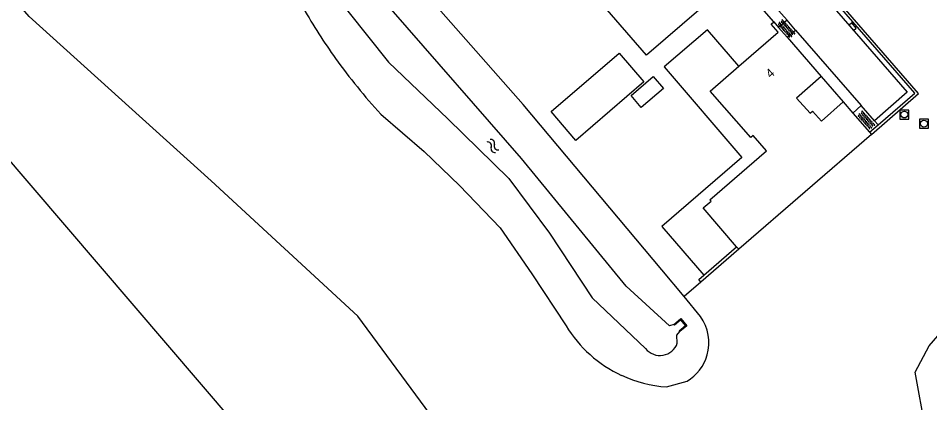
# Model space of a CAD drawing. Extents: x 128999 to 131010, y 395498 to 399007.
# Drawn here: x 129244.5 to 129345.3, y 397421.9 to 397464.4 of the extents above; entities that cross this region are included whole.
import ezdxf

# ---------------------------------------------------------------- set-up
doc = ezdxf.new("R2010")
doc.units = 0
for name, color, linetype in [('gg-afsc-muur', 7, 'Continuous'), ('gg-anno-huisnummerreeks BGT', 7, 'Continuous'), ('gg-bbg-gedigitaliseerde bijgebouw', 7, 'Continuous'), ('gg-bbg-hoofdgebouw', 7, 'Continuous'), ('gg-bbg-luifel en loopbrug', 7, 'Continuous'), ('gg-knt-verharding', 7, 'Continuous'), ('gg-knt-verharding nz', 7, 'Continuous'), ('gg-kntw-bovenkant insteek waterloop', 7, 'Continuous'), ('gg-kntw-midden sloot', 7, 'Continuous'), ('gg-kntw-waterlijn', 7, 'Continuous'), ('gg-kwrk-uitstroombak niveau min 01', 7, 'Continuous'), ('gt-grn-groengrens', 7, 'Continuous'), ('gt-grn-vlakafsluiter', 7, 'Continuous'), ('gt-symb-kolk', 7, 'Continuous'), ('gt-symb-overige verharding', 7, 'Continuous'), ('gt-symb-rioolschacht', 7, 'Continuous'), ('gt-symb-watersymbool', 7, 'Continuous')]:
    doc.layers.add(name, color=color, linetype=linetype)

# ---------------------------------------------------------------- blocks, each defined once
blk = doc.blocks.new('gt0-OVH')
at = {"layer": 'gt-symb-overige verharding'}
for points in [[(-0.97, 0.3), (-0.97, 0.31), (-0.96, 0.32), (-0.97, 0.33), (-0.97, 0.34), (-0.98, 0.35), (-0.99, 0.35), (-1, 0.36), (-1.01, 0.35), (-1.02, 0.35), (-1.03, 0.34), (-1.03, 0.33), (-1.04, 0.32), (-1.03, 0.31), (-1.03, 0.3), (-1.02, 0.29), (-1.01, 0.29), (-1, 0.28), (-0.99, 0.29), (-0.98, 0.29)], [(-0.87, 0.11), (-0.87, 0.12), (-0.86, 0.13), (-0.87, 0.14), (-0.87, 0.15), (-0.88, 0.16), (-0.89, 0.16), (-0.9, 0.16), (-0.91, 0.16), (-0.92, 0.16), (-0.93, 0.15), (-0.93, 0.14), (-0.94, 0.13), (-0.93, 0.12), (-0.93, 0.11), (-0.92, 0.1), (-0.91, 0.09), (-0.9, 0.09), (-0.89, 0.09), (-0.88, 0.1)], [(-0.77, 0.3), (-0.77, 0.31), (-0.76, 0.32), (-0.77, 0.33), (-0.77, 0.34), (-0.78, 0.35), (-0.79, 0.35), (-0.8, 0.36), (-0.81, 0.35), (-0.82, 0.35), (-0.83, 0.34), (-0.83, 0.33), (-0.84, 0.32), (-0.83, 0.31), (-0.83, 0.3), (-0.82, 0.29), (-0.81, 0.29), (-0.8, 0.28), (-0.79, 0.29), (-0.78, 0.29)], [(-0.67, 0.11), (-0.67, 0.12), (-0.66, 0.13), (-0.67, 0.14), (-0.67, 0.15), (-0.68, 0.16), (-0.69, 0.16), (-0.7, 0.16), (-0.71, 0.16), (-0.72, 0.16), (-0.73, 0.15), (-0.73, 0.14), (-0.74, 0.13), (-0.73, 0.12), (-0.73, 0.11), (-0.72, 0.1), (-0.71, 0.09), (-0.7, 0.09), (-0.69, 0.09), (-0.68, 0.1)], [(-0.57, 0.3), (-0.57, 0.31), (-0.56, 0.32), (-0.57, 0.33), (-0.57, 0.34), (-0.58, 0.35), (-0.59, 0.35), (-0.6, 0.36), (-0.61, 0.35), (-0.62, 0.35), (-0.63, 0.34), (-0.63, 0.33), (-0.64, 0.32), (-0.63, 0.31), (-0.63, 0.3), (-0.62, 0.29), (-0.61, 0.29), (-0.6, 0.28), (-0.59, 0.29), (-0.58, 0.29)], [(-0.47, 0.11), (-0.47, 0.12), (-0.46, 0.13), (-0.47, 0.14), (-0.47, 0.15), (-0.48, 0.16), (-0.49, 0.16), (-0.5, 0.16), (-0.51, 0.16), (-0.52, 0.16), (-0.53, 0.15), (-0.53, 0.14), (-0.54, 0.13), (-0.53, 0.12), (-0.53, 0.11), (-0.52, 0.1), (-0.51, 0.09), (-0.5, 0.09), (-0.49, 0.09), (-0.48, 0.1)], [(-0.37, 0.3), (-0.37, 0.31), (-0.36, 0.32), (-0.37, 0.33), (-0.37, 0.34), (-0.38, 0.35), (-0.39, 0.35), (-0.4, 0.36), (-0.41, 0.35), (-0.42, 0.35), (-0.43, 0.34), (-0.43, 0.33), (-0.44, 0.32), (-0.43, 0.31), (-0.43, 0.3), (-0.42, 0.29), (-0.41, 0.29), (-0.4, 0.28), (-0.39, 0.29), (-0.38, 0.29)], [(-0.27, 0.11), (-0.27, 0.12), (-0.26, 0.13), (-0.27, 0.14), (-0.27, 0.15), (-0.28, 0.16), (-0.29, 0.16), (-0.3, 0.16), (-0.31, 0.16), (-0.32, 0.16), (-0.33, 0.15), (-0.33, 0.14), (-0.34, 0.13), (-0.33, 0.12), (-0.33, 0.11), (-0.32, 0.1), (-0.31, 0.09), (-0.3, 0.09), (-0.29, 0.09), (-0.28, 0.1)], [(-0.17, 0.3), (-0.17, 0.31), (-0.16, 0.32), (-0.17, 0.33), (-0.17, 0.34), (-0.18, 0.35), (-0.19, 0.35), (-0.2, 0.36), (-0.21, 0.35), (-0.22, 0.35), (-0.23, 0.34), (-0.23, 0.33), (-0.24, 0.32), (-0.23, 0.31), (-0.23, 0.3), (-0.22, 0.29), (-0.21, 0.29), (-0.2, 0.28), (-0.19, 0.29), (-0.18, 0.29)], [(-0.07, 0.11), (-0.07, 0.12), (-0.06, 0.13), (-0.07, 0.14), (-0.07, 0.15), (-0.08, 0.16), (-0.09, 0.16), (-0.1, 0.16), (-0.11, 0.16), (-0.12, 0.16), (-0.13, 0.15), (-0.13, 0.14), (-0.14, 0.13), (-0.13, 0.12), (-0.13, 0.11), (-0.12, 0.1), (-0.11, 0.09), (-0.1, 0.09), (-0.09, 0.09), (-0.08, 0.1)], [(0.03, 0.3), (0.03, 0.31), (0.04, 0.32), (0.03, 0.33), (0.03, 0.34), (0.02, 0.35), (0.01, 0.35), (0, 0.36), (-0.01, 0.35), (-0.02, 0.35), (-0.03, 0.34), (-0.03, 0.33), (-0.04, 0.32), (-0.03, 0.31), (-0.03, 0.3), (-0.02, 0.29), (-0.01, 0.29), (0, 0.28), (0.01, 0.29), (0.02, 0.29)], [(0.13, 0.11), (0.13, 0.12), (0.14, 0.13), (0.13, 0.14), (0.13, 0.15), (0.12, 0.16), (0.11, 0.16), (0.1, 0.16), (0.09, 0.16), (0.08, 0.16), (0.07, 0.15), (0.07, 0.14), (0.06, 0.13), (0.07, 0.12), (0.07, 0.11), (0.08, 0.1), (0.09, 0.09), (0.1, 0.09), (0.11, 0.09), (0.12, 0.1)], [(0.23, 0.3), (0.23, 0.31), (0.24, 0.32), (0.23, 0.33), (0.23, 0.34), (0.22, 0.35), (0.21, 0.35), (0.2, 0.36), (0.19, 0.35), (0.18, 0.35), (0.17, 0.34), (0.17, 0.33), (0.16, 0.32), (0.17, 0.31), (0.17, 0.3), (0.18, 0.29), (0.19, 0.29), (0.2, 0.28), (0.21, 0.29), (0.22, 0.29)], [(0.33, 0.11), (0.33, 0.12), (0.34, 0.13), (0.33, 0.14), (0.33, 0.15), (0.32, 0.16), (0.31, 0.16), (0.3, 0.16), (0.29, 0.16), (0.28, 0.16), (0.27, 0.15), (0.27, 0.14), (0.26, 0.13), (0.27, 0.12), (0.27, 0.11), (0.28, 0.1), (0.29, 0.09), (0.3, 0.09), (0.31, 0.09), (0.32, 0.1)], [(0.43, 0.3), (0.43, 0.31), (0.44, 0.32), (0.43, 0.33), (0.43, 0.34), (0.42, 0.35), (0.41, 0.35), (0.4, 0.36), (0.39, 0.35), (0.38, 0.35), (0.37, 0.34), (0.37, 0.33), (0.36, 0.32), (0.37, 0.31), (0.37, 0.3), (0.38, 0.29), (0.39, 0.29), (0.4, 0.28), (0.41, 0.29), (0.42, 0.29)], [(0.53, 0.11), (0.53, 0.12), (0.54, 0.13), (0.53, 0.14), (0.53, 0.15), (0.52, 0.16), (0.51, 0.16), (0.5, 0.16), (0.49, 0.16), (0.48, 0.16), (0.47, 0.15), (0.47, 0.14), (0.46, 0.13), (0.47, 0.12), (0.47, 0.11), (0.48, 0.1), (0.49, 0.09), (0.5, 0.09), (0.51, 0.09), (0.52, 0.1)], [(0.63, 0.3), (0.63, 0.31), (0.64, 0.32), (0.63, 0.33), (0.63, 0.34), (0.62, 0.35), (0.61, 0.35), (0.6, 0.36), (0.59, 0.35), (0.58, 0.35), (0.57, 0.34), (0.57, 0.33), (0.56, 0.32), (0.57, 0.31), (0.57, 0.3), (0.58, 0.29), (0.59, 0.29), (0.6, 0.28), (0.61, 0.29), (0.62, 0.29)], [(0.73, 0.11), (0.73, 0.12), (0.74, 0.13), (0.73, 0.14), (0.73, 0.15), (0.72, 0.16), (0.71, 0.16), (0.7, 0.16), (0.69, 0.16), (0.68, 0.16), (0.67, 0.15), (0.67, 0.14), (0.66, 0.13), (0.67, 0.12), (0.67, 0.11), (0.68, 0.1), (0.69, 0.09), (0.7, 0.09), (0.71, 0.09), (0.72, 0.1)], [(0.83, 0.3), (0.83, 0.31), (0.84, 0.32), (0.83, 0.33), (0.83, 0.34), (0.82, 0.35), (0.81, 0.35), (0.8, 0.36), (0.79, 0.35), (0.78, 0.35), (0.77, 0.34), (0.77, 0.33), (0.76, 0.32), (0.77, 0.31), (0.77, 0.3), (0.78, 0.29), (0.79, 0.29), (0.8, 0.28), (0.81, 0.29), (0.82, 0.29)], [(0.93, 0.11), (0.93, 0.12), (0.94, 0.13), (0.93, 0.14), (0.93, 0.15), (0.92, 0.16), (0.91, 0.16), (0.9, 0.16), (0.89, 0.16), (0.88, 0.16), (0.87, 0.15), (0.87, 0.14), (0.86, 0.13), (0.87, 0.12), (0.87, 0.11), (0.88, 0.1), (0.89, 0.09), (0.9, 0.09), (0.91, 0.09), (0.92, 0.1)], [(1.03, 0.3), (1.03, 0.31), (1.04, 0.32), (1.03, 0.33), (1.03, 0.34), (1.02, 0.35), (1.01, 0.35), (1, 0.36), (0.99, 0.35), (0.98, 0.35), (0.97, 0.34), (0.97, 0.33), (0.96, 0.32), (0.97, 0.31), (0.97, 0.3), (0.98, 0.29), (0.99, 0.29), (1, 0.28), (1.01, 0.29), (1.02, 0.29)], [(-0.97, -0.14), (-0.97, -0.13), (-0.96, -0.12), (-0.97, -0.11), (-0.97, -0.1), (-0.98, -0.09), (-0.99, -0.09), (-1, -0.08), (-1.01, -0.09), (-1.02, -0.09), (-1.03, -0.1), (-1.03, -0.11), (-1.04, -0.12), (-1.03, -0.13), (-1.03, -0.14), (-1.02, -0.15), (-1.01, -0.15), (-1, -0.16), (-0.99, -0.15), (-0.98, -0.15)], [(-0.87, -0.33), (-0.87, -0.32), (-0.86, -0.31), (-0.87, -0.3), (-0.87, -0.29), (-0.88, -0.28), (-0.89, -0.28), (-0.9, -0.28), (-0.91, -0.28), (-0.92, -0.28), (-0.93, -0.29), (-0.93, -0.3), (-0.94, -0.31), (-0.93, -0.32), (-0.93, -0.33), (-0.92, -0.34), (-0.91, -0.35), (-0.9, -0.35), (-0.89, -0.35), (-0.88, -0.34)], [(-0.77, -0.14), (-0.77, -0.13), (-0.76, -0.12), (-0.77, -0.11), (-0.77, -0.1), (-0.78, -0.09), (-0.79, -0.09), (-0.8, -0.08), (-0.81, -0.09), (-0.82, -0.09), (-0.83, -0.1), (-0.83, -0.11), (-0.84, -0.12), (-0.83, -0.13), (-0.83, -0.14), (-0.82, -0.15), (-0.81, -0.15), (-0.8, -0.16), (-0.79, -0.15), (-0.78, -0.15)], [(-0.67, -0.33), (-0.67, -0.32), (-0.66, -0.31), (-0.67, -0.3), (-0.67, -0.29), (-0.68, -0.28), (-0.69, -0.28), (-0.7, -0.28), (-0.71, -0.28), (-0.72, -0.28), (-0.73, -0.29), (-0.73, -0.3), (-0.74, -0.31), (-0.73, -0.32), (-0.73, -0.33), (-0.72, -0.34), (-0.71, -0.35), (-0.7, -0.35), (-0.69, -0.35), (-0.68, -0.34)], [(-0.57, -0.14), (-0.57, -0.13), (-0.56, -0.12), (-0.57, -0.11), (-0.57, -0.1), (-0.58, -0.09), (-0.59, -0.09), (-0.6, -0.08), (-0.61, -0.09), (-0.62, -0.09), (-0.63, -0.1), (-0.63, -0.11), (-0.64, -0.12), (-0.63, -0.13), (-0.63, -0.14), (-0.62, -0.15), (-0.61, -0.15), (-0.6, -0.16), (-0.59, -0.15), (-0.58, -0.15)], [(-0.47, -0.33), (-0.47, -0.32), (-0.46, -0.31), (-0.47, -0.3), (-0.47, -0.29), (-0.48, -0.28), (-0.49, -0.28), (-0.5, -0.28), (-0.51, -0.28), (-0.52, -0.28), (-0.53, -0.29), (-0.53, -0.3), (-0.54, -0.31), (-0.53, -0.32), (-0.53, -0.33), (-0.52, -0.34), (-0.51, -0.35), (-0.5, -0.35), (-0.49, -0.35), (-0.48, -0.34)], [(-0.37, -0.14), (-0.37, -0.13), (-0.36, -0.12), (-0.37, -0.11), (-0.37, -0.1), (-0.38, -0.09), (-0.39, -0.09), (-0.4, -0.08), (-0.41, -0.09), (-0.42, -0.09), (-0.43, -0.1), (-0.43, -0.11), (-0.44, -0.12), (-0.43, -0.13), (-0.43, -0.14), (-0.42, -0.15), (-0.41, -0.15), (-0.4, -0.16), (-0.39, -0.15), (-0.38, -0.15)], [(-0.27, -0.33), (-0.27, -0.32), (-0.26, -0.31), (-0.27, -0.3), (-0.27, -0.29), (-0.28, -0.28), (-0.29, -0.28), (-0.3, -0.28), (-0.31, -0.28), (-0.32, -0.28), (-0.33, -0.29), (-0.33, -0.3), (-0.34, -0.31), (-0.33, -0.32), (-0.33, -0.33), (-0.32, -0.34), (-0.31, -0.35), (-0.3, -0.35), (-0.29, -0.35), (-0.28, -0.34)], [(-0.17, -0.14), (-0.17, -0.13), (-0.16, -0.12), (-0.17, -0.11), (-0.17, -0.1), (-0.18, -0.09), (-0.19, -0.09), (-0.2, -0.08), (-0.21, -0.09), (-0.22, -0.09), (-0.23, -0.1), (-0.23, -0.11), (-0.24, -0.12), (-0.23, -0.13), (-0.23, -0.14), (-0.22, -0.15), (-0.21, -0.15), (-0.2, -0.16), (-0.19, -0.15), (-0.18, -0.15)], [(-0.07, -0.33), (-0.07, -0.32), (-0.06, -0.31), (-0.07, -0.3), (-0.07, -0.29), (-0.08, -0.28), (-0.09, -0.28), (-0.1, -0.28), (-0.11, -0.28), (-0.12, -0.28), (-0.13, -0.29), (-0.13, -0.3), (-0.14, -0.31), (-0.13, -0.32), (-0.13, -0.33), (-0.12, -0.34), (-0.11, -0.35), (-0.1, -0.35), (-0.09, -0.35), (-0.08, -0.34)], [(0.03, -0.14), (0.03, -0.13), (0.04, -0.12), (0.03, -0.11), (0.03, -0.1), (0.02, -0.09), (0.01, -0.09), (0, -0.08), (-0.01, -0.09), (-0.02, -0.09), (-0.03, -0.1), (-0.03, -0.11), (-0.04, -0.12), (-0.03, -0.13), (-0.03, -0.14), (-0.02, -0.15), (-0.01, -0.15), (0, -0.16), (0.01, -0.15), (0.02, -0.15)], [(0.13, -0.33), (0.13, -0.32), (0.14, -0.31), (0.13, -0.3), (0.13, -0.29), (0.12, -0.28), (0.11, -0.28), (0.1, -0.28), (0.09, -0.28), (0.08, -0.28), (0.07, -0.29), (0.07, -0.3), (0.06, -0.31), (0.07, -0.32), (0.07, -0.33), (0.08, -0.34), (0.09, -0.35), (0.1, -0.35), (0.11, -0.35), (0.12, -0.34)], [(0.23, -0.14), (0.23, -0.13), (0.24, -0.12), (0.23, -0.11), (0.23, -0.1), (0.22, -0.09), (0.21, -0.09), (0.2, -0.08), (0.19, -0.09), (0.18, -0.09), (0.17, -0.1), (0.17, -0.11), (0.16, -0.12), (0.17, -0.13), (0.17, -0.14), (0.18, -0.15), (0.19, -0.15), (0.2, -0.16), (0.21, -0.15), (0.22, -0.15)], [(0.33, -0.33), (0.33, -0.32), (0.34, -0.31), (0.33, -0.3), (0.33, -0.29), (0.32, -0.28), (0.31, -0.28), (0.3, -0.28), (0.29, -0.28), (0.28, -0.28), (0.27, -0.29), (0.27, -0.3), (0.26, -0.31), (0.27, -0.32), (0.27, -0.33), (0.28, -0.34), (0.29, -0.35), (0.3, -0.35), (0.31, -0.35), (0.32, -0.34)], [(0.43, -0.14), (0.43, -0.13), (0.44, -0.12), (0.43, -0.11), (0.43, -0.1), (0.42, -0.09), (0.41, -0.09), (0.4, -0.08), (0.39, -0.09), (0.38, -0.09), (0.37, -0.1), (0.37, -0.11), (0.36, -0.12), (0.37, -0.13), (0.37, -0.14), (0.38, -0.15), (0.39, -0.15), (0.4, -0.16), (0.41, -0.15), (0.42, -0.15)], [(0.53, -0.33), (0.53, -0.32), (0.54, -0.31), (0.53, -0.3), (0.53, -0.29), (0.52, -0.28), (0.51, -0.28), (0.5, -0.28), (0.49, -0.28), (0.48, -0.28), (0.47, -0.29), (0.47, -0.3), (0.46, -0.31), (0.47, -0.32), (0.47, -0.33), (0.48, -0.34), (0.49, -0.35), (0.5, -0.35), (0.51, -0.35), (0.52, -0.34)], [(0.63, -0.14), (0.63, -0.13), (0.64, -0.12), (0.63, -0.11), (0.63, -0.1), (0.62, -0.09), (0.61, -0.09), (0.6, -0.08), (0.59, -0.09), (0.58, -0.09), (0.57, -0.1), (0.57, -0.11), (0.56, -0.12), (0.57, -0.13), (0.57, -0.14), (0.58, -0.15), (0.59, -0.15), (0.6, -0.16), (0.61, -0.15), (0.62, -0.15)], [(0.73, -0.33), (0.73, -0.32), (0.74, -0.31), (0.73, -0.3), (0.73, -0.29), (0.72, -0.28), (0.71, -0.28), (0.7, -0.28), (0.69, -0.28), (0.68, -0.28), (0.67, -0.29), (0.67, -0.3), (0.66, -0.31), (0.67, -0.32), (0.67, -0.33), (0.68, -0.34), (0.69, -0.35), (0.7, -0.35), (0.71, -0.35), (0.72, -0.34)], [(0.83, -0.14), (0.83, -0.13), (0.84, -0.12), (0.83, -0.11), (0.83, -0.1), (0.82, -0.09), (0.81, -0.09), (0.8, -0.08), (0.79, -0.09), (0.78, -0.09), (0.77, -0.1), (0.77, -0.11), (0.76, -0.12), (0.77, -0.13), (0.77, -0.14), (0.78, -0.15), (0.79, -0.15), (0.8, -0.16), (0.81, -0.15), (0.82, -0.15)], [(0.93, -0.33), (0.93, -0.32), (0.94, -0.31), (0.93, -0.3), (0.93, -0.29), (0.92, -0.28), (0.91, -0.28), (0.9, -0.28), (0.89, -0.28), (0.88, -0.28), (0.87, -0.29), (0.87, -0.3), (0.86, -0.31), (0.87, -0.32), (0.87, -0.33), (0.88, -0.34), (0.89, -0.35), (0.9, -0.35), (0.91, -0.35), (0.92, -0.34)], [(1.03, -0.14), (1.03, -0.13), (1.04, -0.12), (1.03, -0.11), (1.03, -0.1), (1.02, -0.09), (1.01, -0.09), (1, -0.08), (0.99, -0.09), (0.98, -0.09), (0.97, -0.1), (0.97, -0.11), (0.96, -0.12), (0.97, -0.13), (0.97, -0.14), (0.98, -0.15), (0.99, -0.15), (1, -0.16), (1.01, -0.15), (1.02, -0.15)]]:
    blk.add_lwpolyline(points, close=True, dxfattribs=at)
blk = doc.blocks.new('gt0-RS')
at = {"layer": 'gt-symb-rioolschacht'}
blk.add_lwpolyline([(-0.5, -0.5), (0.5, -0.5), (0.5, 0.5), (-0.5, 0.5)], close=True, dxfattribs=at)
blk.add_circle((0, 0), 0.375, dxfattribs=at)
blk = doc.blocks.new('gt0-WA')
at = {"layer": 'gt-symb-watersymbool'}
for centre, start, end in [((-0.32, 0.02), 28.0725, 151.9275), ((0.43, 0.42), 208.0725, 331.9275), ((-0.32, -0.43), 28.0725, 151.9275), ((0.43, -0.03), 208.0725, 331.9275)]:
    blk.add_arc(centre, 0.425, start, end, dxfattribs=at)
blk = doc.blocks.new('gt0-KOLK')
at = {"layer": 'gt-symb-kolk'}
blk.add_lwpolyline([(0, 0), (0.38, 0), (0.38, 0.4), (-0.38, 0.4), (-0.38, 0), (0, 0)], dxfattribs=at)

msp = doc.modelspace()

# ---------------------------------------------------------------- linework, layer by layer
at = {"layer": 'gg-afsc-muur'}
for p, q in [((129338.62, 397451.82), (129339.56, 397452.64)), ((129324.16, 397438.9), (129319.98, 397435.28))]:
    msp.add_line(p, q, dxfattribs=at)
for points in [[(129339.56, 397452.64), (129343.61, 397456.15), (129293.45, 397513.91)], [(129338.82, 397451.59), (129344.01, 397456.11), (129293.67, 397514.09), (129293.6, 397514.03)], [(129319.98, 397435.28), (129319.74, 397435.57), (129320.29, 397436.05)]]:
    msp.add_lwpolyline(points, dxfattribs=at)
at = {"layer": 'gg-bbg-gedigitaliseerde bijgebouw'}
for points in [[(129303.44, 397454.11), (129310.93, 397460.56), (129313.66, 397457.38), (129306.17, 397450.93), (129303.44, 397454.11)], [(129312.26, 397455.87), (129314.7, 397457.97), (129315.83, 397456.65), (129313.39, 397454.56), (129312.26, 397455.87)]]:
    msp.add_lwpolyline(points, dxfattribs=at)
at = {"layer": 'gg-bbg-hoofdgebouw'}
for p, q in [((129328.04, 397464.01), (129328.57, 397463.4)), ((129328.57, 397463.4), (129329.5, 397462.33)), ((129329.5, 397462.33), (129333.26, 397457.98)), ((129335.69, 397455.19), (129336.77, 397453.95)), ((129336.77, 397453.95), (129338.62, 397451.82)), ((129338.82, 397451.59), (129324.16, 397438.9)), ((129338.62, 397451.82), (129338.82, 397451.59)), ((129323.91, 397439.18), (129324.16, 397438.9))]:
    msp.add_line(p, q, dxfattribs=at)
for points in [[(129321.79, 397471.19), (129321.51, 397470.94), (129321.33, 397471.14), (129317.84, 397468.11), (129320, 397465.52), (129313.98, 397460.34), (129307.18, 397468.2)], [(129324.17, 397459.11), (129328.51, 397462.87), (129327.75, 397463.75), (129328.04, 397464.01)], [(129323.91, 397439.18), (129320.24, 397443.47), (129321.11, 397444.22), (129320.98, 397444.37), (129327.23, 397449.79), (129325.76, 397451.48), (129325.48, 397451.24), (129321.01, 397456.38), (129324.17, 397459.11)], [(129333.26, 397457.98), (129330.56, 397455.61), (129332.04, 397453.92), (129332.31, 397454.16), (129333.3, 397453.05), (129335.69, 397455.19)]]:
    msp.add_lwpolyline(points, dxfattribs=at)
at = {"layer": 'gg-bbg-luifel en loopbrug'}
msp.add_line((129320.29, 397436.05), (129323.91, 397439.18), dxfattribs=at)
msp.add_lwpolyline([(129324.17, 397459.11), (129320.7, 397463.15), (129315.92, 397459.04), (129324.51, 397449.05), (129315.65, 397441.43), (129320.29, 397436.05)], dxfattribs=at)
at = {"layer": 'gg-knt-verharding'}
for p, q in [((129328.04, 397464.01), (129321.79, 397471.19)), ((129329.51, 397464.21), (129328.57, 397463.4)), ((129330.44, 397463.12), (129329.51, 397464.21)), ((129329.5, 397462.33), (129330.44, 397463.12)), ((129333.26, 397457.98), (129335.69, 397455.19)), ((129337.69, 397454.77), (129336.77, 397453.95)), ((129339.16, 397453.09), (129337.69, 397454.77)), ((129339.16, 397453.09), (129339.56, 397452.64))]:
    msp.add_line(p, q, dxfattribs=at)
msp.add_lwpolyline([(129293.01, 397513.55), (129342.78, 397456.24), (129339.16, 397453.09)], dxfattribs=at)
at = {"layer": 'gg-knt-verharding nz'}
for p, q in [((129329.51, 397464.21), (129321.7, 397473.18)), ((129330.44, 397463.12), (129337.69, 397454.77))]:
    msp.add_line(p, q, dxfattribs=at)
at = {"layer": 'gg-kntw-bovenkant insteek waterloop'}
for p, q in [((129319.95, 397431.46), (129318.12, 397433.68)), ((129316.18, 397423.68), (129318.45, 397424.31))]:
    msp.add_line(p, q, dxfattribs=at)
for points in [[(129318.12, 397433.68), (129315.67, 397436.63), (129300.35, 397454.89), (129284.89, 397472.43), (129273.71, 397484.65), (129269.01, 397490.89)], [(129284.59, 397453.81), (129289.41, 397449.71), (129293.3, 397445.94), (129297.78, 397441.25), (129301.28, 397436.17), (129305.08, 397430.45)], [(129376.5, 397433.58), (129380.7, 397432.48), (129382.93, 397430.88), (129386.13, 397426.66), (129386.97, 397421.78), (129385.36, 397415.89), (129381.92, 397411.5), (129377.31, 397408.84), (129373.04, 397407.77), (129366.6, 397407.37), (129356.13, 397409.28), (129350.93, 397411.08), (129346.58, 397414.83), (129344.8, 397419.06), (129343.66, 397425.31), (129345.22, 397428.24), (129347.82, 397431.23), (129352.41, 397433.27), (129358.81, 397434.6), (129376.5, 397433.58)]]:
    msp.add_lwpolyline(points, dxfattribs=at)
for centre, radius, start, end in [((129334.34, 397499.05), 67.25, 209.904, 215.5236), ((129334.04, 397498.88), 66.9, 215.5511, 222.3442), ((129315.87, 397428.58), 4.99, 344.183, 35.2023), ((129317.2, 397437.85), 14.21, 211.3951, 245.0427), ((129315.87, 397428.58), 4.99, 301.0749, 344.1714), ((129317.2, 397437.85), 14.2, 245.0606, 265.9041)]:
    msp.add_arc(centre, radius, start, end, dxfattribs=at)
at = {"layer": 'gg-kntw-midden sloot'}
msp.add_line((129328.36, 397349.84), (129202.93, 397496.1), dxfattribs=at)
at = {"layer": 'gg-kntw-waterlijn'}
for points in [[(129317, 397430.59), (129316.5, 397430.43), (129311.71, 397434.83), (129300.15, 397448.92), (129285.74, 397465.42), (129277.5, 397474.65), (129266.69, 397485.84), (129263.56, 397488.27), (129261.44, 397491.39)], [(129255.99, 397489.84), (129259.63, 397487.49), (129261.24, 397486.53), (129262.81, 397485.52), (129264.52, 397484.37), (129266.19, 397483.17), (129269.8, 397479.19), (129274.35, 397473.86), (129280.95, 397465.21), (129285.46, 397459.56), (129292, 397453.3), (129298.76, 397446.7), (129303.23, 397440.68), (129307.95, 397433.52), (129313.86, 397427.93)], [(129317.37, 397428.53), (129317.33, 397429.42), (129317.64, 397429.82)]]:
    msp.add_lwpolyline(points, dxfattribs=at)
for start, end in [(218.3401, 279.9093), (279.9611, 341.1332)]:
    msp.add_arc((129315.45, 397429.19), 2.03, start, end, dxfattribs=at)
at = {"layer": 'gg-kwrk-uitstroombak niveau min 01'}
for points in [[(129317, 397430.59), (129317.77, 397431.23), (129318.41, 397430.45), (129317.64, 397429.82)], [(129317.64, 397429.82), (129317.58, 397429.9), (129318.27, 397430.47), (129317.76, 397431.09), (129317.06, 397430.52), (129317, 397430.59)]]:
    msp.add_lwpolyline(points, dxfattribs=at)
at = {"layer": 'gt-grn-groengrens'}
msp.add_lwpolyline([(129310.83, 397401.47), (129308.04, 397404.26), (129291.17, 397419.18), (129282.08, 397431.51), (129265.86, 397446.44), (129245.74, 397464.61), (129232.76, 397479.53), (129211.35, 397497.7), (129181.5, 397535.99), (129170.42, 397548.18)], dxfattribs=at)
at = {"layer": 'gt-grn-vlakafsluiter'}
msp.add_line((129319.98, 397435.28), (129318.12, 397433.68), dxfattribs=at)

# ---------------------------------------------------------------- block references
at = {"layer": 'gt-symb-kolk', "rotation": -49.031951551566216}
msp.add_blockref('gt0-KOLK', (129336.6, 397463.36), dxfattribs=at)
at = {"layer": 'gt-symb-overige verharding', "rotation": -47.79566231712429}
for p in [(129329.41, 397463.27), (129338.24, 397453.16)]:
    msp.add_blockref('gt0-OVH', p, dxfattribs=at)
at = {"layer": 'gt-symb-rioolschacht'}
for p in [(129342.46, 397453.78), (129344.63, 397452.78)]:
    msp.add_blockref('gt0-RS', p, dxfattribs=at)
at = {"layer": 'gt-symb-watersymbool', "rotation": -50.113699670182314}
msp.add_blockref('gt0-WA', (129296.95, 397450.36), dxfattribs=at)

# ---------------------------------------------------------------- texts
at = {"layer": 'gg-anno-huisnummerreeks BGT'}
msp.add_text('4', height=1, rotation=40.9, dxfattribs=at).set_placement((129327.66, 397457.74))

doc.saveas('drawing.dxf')
